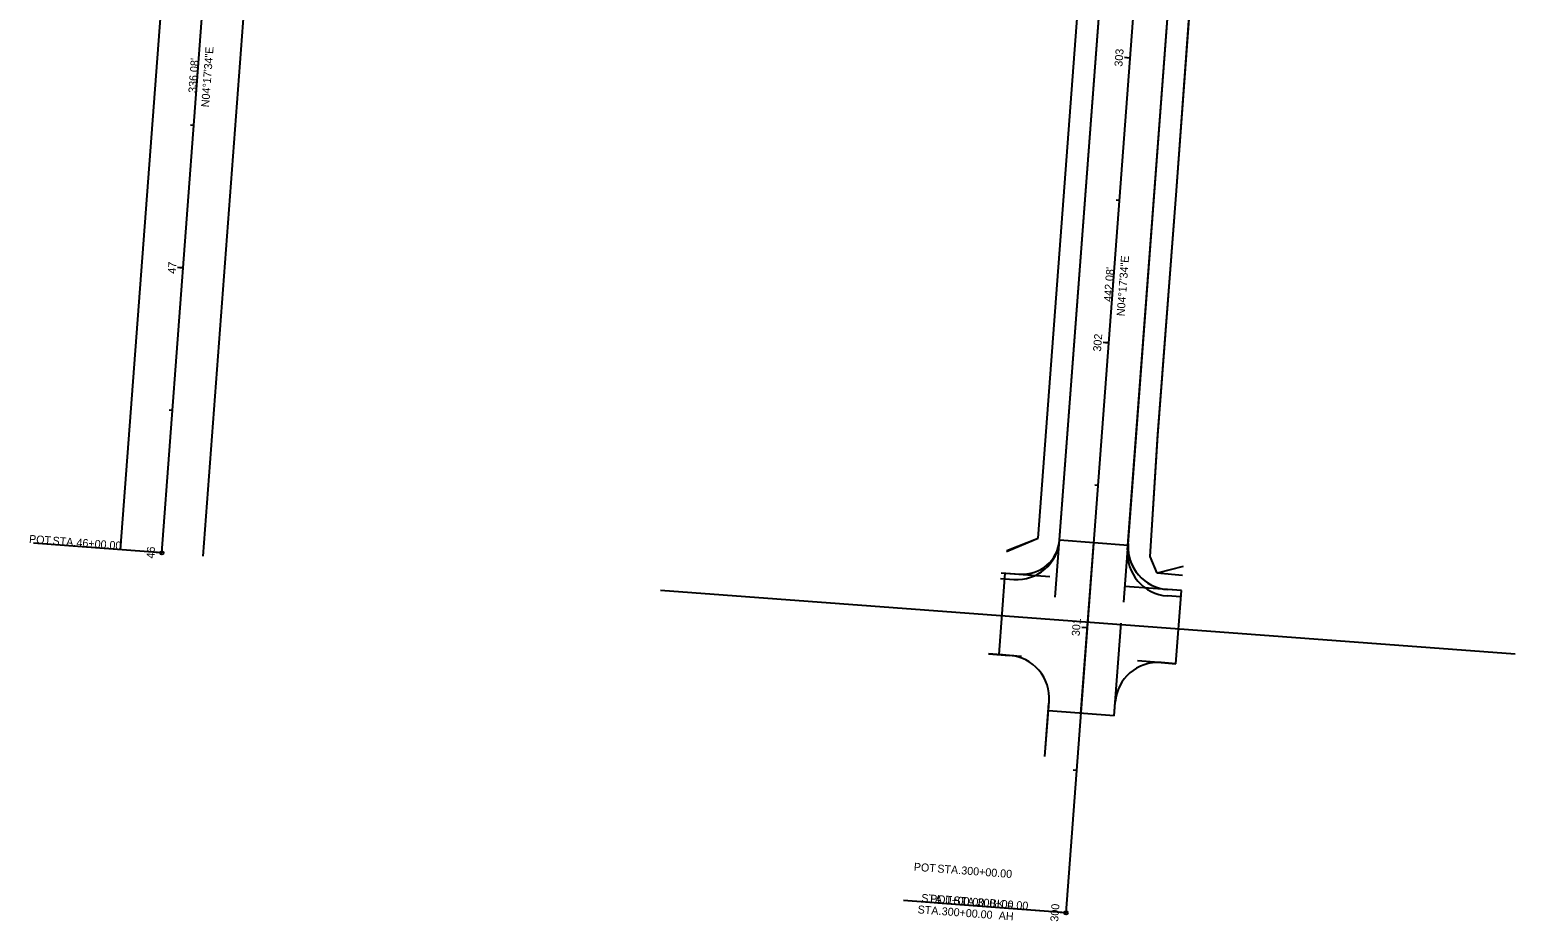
# Model space of a CAD drawing. Extents: x 219353 to 221640, y 361458 to 364236.
# Drawn here: x 220157 to 220677, y 361458 to 361770 of the extents above; entities that cross this region are included whole.
import ezdxf

# ---------------------------------------------------------------- set-up
doc = ezdxf.new("R2010")
doc.units = 0
for name, color, linetype in [('Default', 7, 'Continuous'), ('DR_P_Cells', 7, 'Continuous'), ('DR_P_GenericNode', 7, 'Continuous'), ('DR_X_Cells', 7, 'Continuous'), ('DR_X_GenericNode', 7, 'Continuous'), ('DT_X_Contour_Major', 7, 'Continuous'), ('DT_X_Contour_Minor', 7, 'Continuous'), ('SC_ProfileRun1', 7, 'Continuous'), ('SC_ProfileRun2', 7, 'Continuous'), ('SC_ProfileRun3', 7, 'Continuous'), ('SC_Scratch1', 7, 'Continuous'), ('UT_X_San_Storm_Line', 7, 'Continuous'), ('UT_X_Sanitary_Cells', 7, 'Continuous'), ('UT_X_Sanitary_Line', 7, 'Continuous')]:
    doc.layers.add(name, color=color, linetype=linetype)

msp = doc.modelspace()

# ---------------------------------------------------------------- linework, layer by layer
at = {"layer": 'Default'}
for p, q in [((220558.36, 361711.68), (220563.26, 361779.19)), ((220551.88, 361627.62), (220558.36, 361711.68)), ((220549.25, 361585.3), (220551.88, 361627.62)), ((220551.71, 361579.43), (220549.25, 361585.3)), ((220560.82, 361581.81), (220551.71, 361579.43))]:
    msp.add_line(p, q, dxfattribs=at)
at = {"layer": 'DR_X_Cells'}
for p, q in [((220203.38, 361586.53), (220158.5, 361589.9)), ((220519.79, 361460.55), (220462.95, 361464.82)), ((220519.79, 361460.55), (220474.92, 361463.92))]:
    msp.add_line(p, q, dxfattribs=at)
for centre in [(220203.38, 361586.53), (220519.79, 361460.55), (220519.79, 361460.55)]:
    msp.add_circle(centre, 0.6, dxfattribs=at)
at = {"layer": 'DR_X_GenericNode'}
for p, q in [((220517.55, 361591.08), (220540.92, 361902.41)), ((220541.36, 361587.55), (220564.84, 361900.37)), ((220510.07, 361591.64), (220525.91, 361802.55)), ((220510.08, 361591.64), (220525.87, 361802.05)), ((220558.36, 361711.68), (220563.3, 361779.69)), ((220551.92, 361628.11), (220558.36, 361711.68)), ((220549.25, 361585.3), (220551.92, 361628.11)), ((220498.99, 361586.96), (220510.07, 361591.64)), ((220499.05, 361587.39), (220510.08, 361591.64)), ((220551.71, 361579.43), (220549.25, 361585.3)), ((220496.89, 361577.59), (220501.48, 361577.25)), ((220560.58, 361578.58), (220551.71, 361579.43)), ((220560.03, 361571.1), (220555.2, 361571.46))]:
    msp.add_line(p, q, dxfattribs=at)
for centre, start, end in [((220502.6, 361592.2), 265.7335, 355.7073), ((220556.31, 361586.42), 175.7073, 265.7335)]:
    msp.add_arc(centre, 15, start, end, dxfattribs=at)
at = {"layer": 'DT_X_Contour_Major'}
for p, q in [((220203.38, 361586.53), (220228.53, 361921.67)), ((220519.79, 361460.55), (220552.88, 361901.39)), ((220203.38, 361586.53), (220223.37, 361852.86)), ((220377.85, 361573.51), (220677.02, 361551.19))]:
    msp.add_line(p, q, dxfattribs=at)
at = {"layer": 'DT_X_Contour_Minor'}
for p, q in [((220188.92, 361587.61), (220214.07, 361922.75)), ((220188.92, 361587.61), (220214.07, 361922.75)), ((220188.92, 361587.61), (220214.07, 361922.75)), ((220217.83, 361585.44), (220242.99, 361920.58)), ((220217.83, 361585.44), (220242.99, 361920.58)), ((220217.83, 361585.44), (220242.99, 361920.58)), ((220516.05, 361571.09), (220540.92, 361902.41)), ((220516.05, 361571.09), (220540.92, 361902.41)), ((220517.55, 361591.08), (220540.92, 361902.41)), ((220517.55, 361591.08), (220540.92, 361902.41)), ((220539.99, 361569.29), (220564.84, 361900.37)), ((220539.99, 361569.29), (220564.84, 361900.37)), ((220541.52, 361589.77), (220564.84, 361900.37)), ((220541.52, 361589.77), (220564.84, 361900.37)), ((220517.55, 361591.08), (220541.49, 361589.29)), ((220525.03, 361530.35), (220529.52, 361590.18)), ((220497.04, 361579.58), (220514.11, 361578.31)), ((220497.04, 361579.58), (220503.62, 361579.09)), ((220497.04, 361579.58), (220503.62, 361579.09)), ((220560.2, 361573.33), (220540.43, 361574.81)), ((220560.2, 361573.33), (220555.37, 361573.69)), ((220560.2, 361573.33), (220555.37, 361573.69)), ((220536.63, 361529.48), (220539.07, 361561.96)), ((220492.71, 361551.2), (220504.23, 361550.34)), ((220492.71, 361551.2), (220500.03, 361550.65)), ((220500.03, 361550.65), (220492.71, 361551.2)), ((220558.28, 361547.73), (220544.75, 361548.74)), ((220558.28, 361547.73), (220553.06, 361548.12)), ((220553.06, 361548.12), (220558.28, 361547.73)), ((220512.43, 361515.31), (220513.87, 361534.57)), ((220512.43, 361515.31), (220513.87, 361534.57)), ((220512.43, 361515.31), (220513.82, 361533.89)), ((220536.63, 361529.48), (220536.99, 361534.29)), ((220536.63, 361529.48), (220536.99, 361534.29))]:
    msp.add_line(p, q, dxfattribs=at)
for centre, radius, start, end in [((220504.59, 361592.06), 13, 265.7335, 355.7073), ((220504.59, 361592.06), 13, 265.7335, 355.7073), ((220556.48, 361588.65), 15, 175.7073, 265.7335), ((220556.48, 361588.65), 15, 175.7073, 265.7335), ((220498.92, 361535.69), 15, 355.7073, 85.7335), ((220498.92, 361535.69), 15, 355.7073, 85.7335), ((220551.95, 361533.17), 15, 85.7335, 175.7073), ((220551.95, 361533.17), 15, 85.7335, 175.7073)]:
    msp.add_arc(centre, radius, start, end, dxfattribs=at)
at = {"layer": 'SC_ProfileRun2'}
for p, q in [((220203.38, 361586.53), (220158.5, 361589.9)), ((220203.38, 361586.53), (220158.5, 361589.9)), ((220519.79, 361460.55), (220462.95, 361464.82)), ((220519.79, 361460.55), (220474.92, 361463.92))]:
    msp.add_line(p, q, dxfattribs=at)
for centre in [(220203.38, 361586.53), (220203.38, 361586.53), (220519.79, 361460.55), (220519.79, 361460.55)]:
    msp.add_circle(centre, 0.6, dxfattribs=at)
at = {"layer": 'SC_ProfileRun3'}
for p, q in [((220542.25, 361759.71), (220541.05, 361759.8)), ((220210.86, 361686.25), (220209.66, 361686.34)), ((220210.86, 361686.25), (220209.66, 361686.34)), ((220534.76, 361659.99), (220533.56, 361660.08)), ((220203.38, 361586.53), (220202.18, 361586.62)), ((220203.38, 361586.53), (220202.18, 361586.62)), ((220527.27, 361560.27), (220526.08, 361560.36)), ((220519.79, 361460.55), (220517.8, 361460.7))]:
    msp.add_line(p, q, dxfattribs=at)
at = {"layer": 'UT_X_San_Storm_Line'}
for p, q in [((220498.43, 361579.48), (220503.62, 361579.09)), ((220560.19, 361573.33), (220555.37, 361573.69)), ((220500.03, 361550.65), (220496.3, 361550.93)), ((220553.06, 361548.12), (220558.28, 361547.73)), ((220513.62, 361531.21), (220513.87, 361534.57)), ((220536.63, 361529.48), (220536.99, 361534.29))]:
    msp.add_line(p, q, dxfattribs=at)
for centre, radius, start, end in [((220504.59, 361592.06), 13, 265.7335, 355.7073), ((220556.48, 361588.65), 15, 177.5763, 265.7335), ((220498.92, 361535.69), 15, 355.7073, 85.7335), ((220551.95, 361533.17), 15, 85.7335, 175.7073)]:
    msp.add_arc(centre, radius, start, end, dxfattribs=at)
at = {"layer": 'UT_X_Sanitary_Cells'}
for p, q in [((220542.25, 361759.71), (220540.25, 361759.86)), ((220214.6, 361736.11), (220213.41, 361736.2)), ((220538.5, 361709.85), (220537.31, 361709.94)), ((220210.86, 361686.25), (220208.87, 361686.4)), ((220534.76, 361659.99), (220532.77, 361660.14)), ((220207.12, 361636.39), (220205.92, 361636.48)), ((220531.02, 361610.13), (220529.82, 361610.22)), ((220203.38, 361586.53), (220201.38, 361586.68)), ((220527.27, 361560.27), (220525.28, 361560.42)), ((220523.53, 361510.41), (220522.34, 361510.5)), ((220519.79, 361460.55), (220517.8, 361460.7)), ((220519.79, 361460.55), (220517.8, 361460.7))]:
    msp.add_line(p, q, dxfattribs=at)
at = {"layer": 'UT_X_Sanitary_Line'}
for p, q in [((220498.43, 361579.48), (220496.3, 361550.93)), ((220558.28, 361547.73), (220560.19, 361573.33)), ((220536.7, 361529.48), (220513.62, 361531.21))]:
    msp.add_line(p, q, dxfattribs=at)

# ---------------------------------------------------------------- texts
at = {"layer": 'DR_P_Cells'}
for s, p in [("336.08'", (220215.41, 361747.44)), ("442.08'", (220535.79, 361674.31))]:
    msp.add_text(s, height=2.8, rotation=85.7073, dxfattribs=at).set_placement(p)
at = {"layer": 'DR_P_GenericNode'}
for s, p in [("336.08'", (220215.41, 361747.44)), ("336.08'", (220215.41, 361747.44)), ("442.08'", (220535.79, 361674.31))]:
    msp.add_text(s, height=2.8, rotation=85.7073, dxfattribs=at).set_placement(p)
at = {"layer": 'DR_X_Cells'}
for s, p in [('POT', (220156.83, 361590.07)), (' STA. ', (220164.01, 361589.53)), ('46+00.00', (220173.43, 361588.82)), ('STA. ', (220469.06, 361464.4)), ('POT', (220472.13, 361464.17)), ('0+00.00', (220477.49, 361463.77)), (' STA. ', (220479.31, 361463.63)), ('300+00.00', (220488.73, 361462.92)), (' BK =', (220491.93, 361462.68)), ('STA. ', (220467.79, 361460.39)), ('300+00.00', (220476.22, 361459.76)), (' AH', (220495.12, 361458.34))]:
    msp.add_text(s, height=2.8, rotation=355.7073, dxfattribs=at).set_placement(p)
at = {"layer": 'SC_ProfileRun1'}
for p in [(220219.89, 361742.41), (220219.89, 361742.41), (220540.27, 361669.28)]:
    msp.add_text('N04°17\'34"E', height=2.8, rotation=85.7073, dxfattribs=at).set_placement(p)
at = {"layer": 'SC_ProfileRun2'}
for s, p in [('POT', (220156.83, 361590.07)), ('POT', (220156.83, 361590.07)), (' STA. ', (220164.01, 361589.53)), (' STA. ', (220164.01, 361589.53)), ('46+00.00', (220173.43, 361588.82)), ('46+00.00', (220173.43, 361588.82)), ('POT', (220466.45, 361475.31)), (' STA. ', (220473.64, 361474.77)), ('300+00.00', (220483.06, 361474.06)), ('STA. ', (220469.06, 361464.4)), ('0+00.00', (220477.49, 361463.77)), (' BK =', (220491.93, 361462.68)), ('STA. ', (220467.79, 361460.39)), ('300+00.00', (220476.22, 361459.76)), (' AH', (220495.12, 361458.34))]:
    msp.add_text(s, height=2.8, rotation=355.7073, dxfattribs=at).set_placement(p)
at = {"layer": 'SC_ProfileRun3'}
msp.add_text('300', height=2.8, rotation=85.7073, dxfattribs=at).set_placement((220517.05, 361457.4))
at = {"layer": 'SC_Scratch1'}
for p in [(220219.89, 361742.41), (220540.27, 361669.28)]:
    msp.add_text('N04°17\'34"E', height=2.8, rotation=85.7073, dxfattribs=at).set_placement(p)
at = {"layer": 'UT_X_Sanitary_Cells'}
for s, p in [('303', (220539.51, 361756.63)), ('47', (220208.2, 361684.14)), ('302', (220532.02, 361656.9)), ('46', (220200.71, 361584.48)), ('301', (220524.55, 361557.31)), ('300', (220517.05, 361457.4)), ('300', (220517.05, 361457.4))]:
    msp.add_text(s, height=2.8, rotation=85.7073, dxfattribs=at).set_placement(p)

doc.saveas('drawing.dxf')
